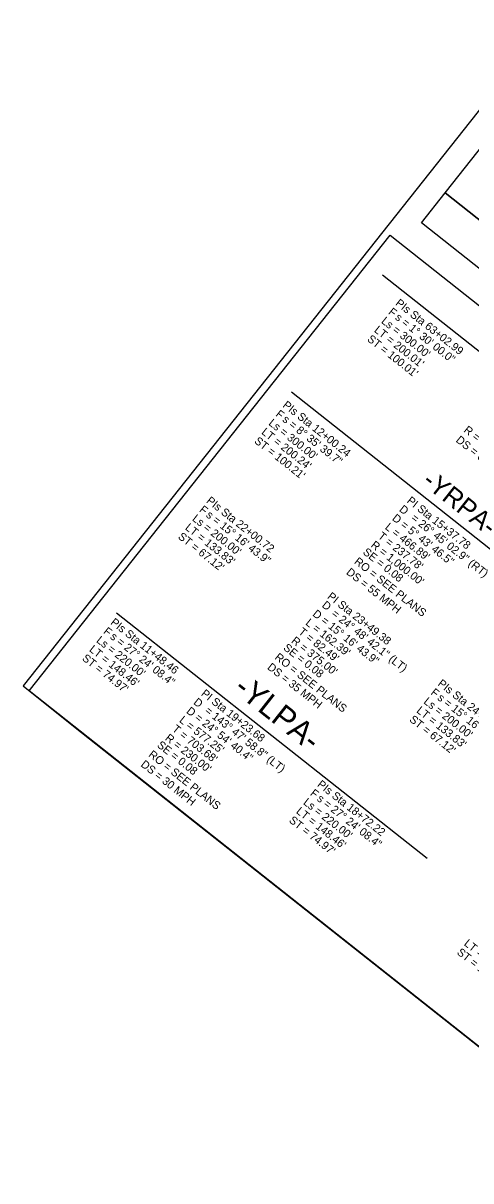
# Model space of a CAD drawing. Extents: x 1771636 to 1784627, y 798645 to 819978.
# Drawn here: x 1782923 to 1783314, y 812169 to 813181 of the extents above; entities that cross this region are included whole.
import ezdxf

# ---------------------------------------------------------------- set-up
doc = ezdxf.new("R2010")
doc.units = 0
for name, color, linetype in [('Exist Utilities Sanitary Sewer Manhole CELL', 7, 'Continuous'), ('Exist Utilities Telephone Pole CELL', 7, 'Continuous'), ('Exist Utilities Water Fire Hydrant CELL', 7, 'Continuous'), ('Exist Vegetation Woods Line', 7, 'Continuous')]:
    doc.layers.add(name, color=color, linetype=linetype)

msp = doc.modelspace()

# ---------------------------------------------------------------- linework, layer by layer
at = {"layer": 'Exist Utilities Telephone Pole CELL'}
msp.add_lwpolyline([(1783384.7, 813185.4), (1782922.7, 812601.8), (1782968.4, 812565.5), (1783541, 812112.3), (1783700.5, 812313.7), (1783949.3, 812116.7), (1783784.1, 811908), (1783320.2, 811324), (1783286.6, 811356.7), (1783146.9, 811467.3), (1783125.1, 811467.6), (1783094.1, 811428.4), (1782948.7, 811547.7), (1782956.1, 811557), (1782756.8, 811714.8), (1782728.2, 811696), (1782447, 811920.2), (1782412.5, 811881.5), (1782072.9, 812146.5), (1782110.3, 812188.5), (1781507.5, 812669.1)], dxfattribs=at)
at = {"layer": 'Exist Utilities Water Fire Hydrant CELL'}
for p, q in [((1783236.9, 812961.2), (1783435.3, 812804.1)), ((1783157.4, 812858.8), (1783432, 812641.4)), ((1783004.5, 812665.8), (1783275.8, 812451))]:
    msp.add_line(p, q, dxfattribs=at)
at = {"layer": 'Exist Vegetation Woods Line'}
for points in [[(1783405.8, 813177.4), (1784088, 812637.3), (1783973.7, 812492.9), (1783291.5, 813033)], [(1783291.5, 813033), (1783973.7, 812492.9), (1783952.9, 812466.7), (1783270.8, 813006.7)], [(1783243.6, 812995.9), (1784039.7, 812365.6), (1783883.7, 812168.7), (1783700.5, 812313.7), (1783541, 812112.3), (1782928.1, 812597.5)]]:
    msp.add_lwpolyline(points, close=True, dxfattribs=at)

# ---------------------------------------------------------------- texts
at = {"layer": 'Exist Utilities Sanitary Sewer Manhole CELL'}
for s, rotation, p in [('PIs Sta 63+02.99', 321.7188, (1783247.6, 812935.4)), ('F', 321.7188, (1783241.4, 812927.6)), ("Ls = 300.00'", 321.7188, (1783235.2, 812919.7)), ('s = 1%%d 30\' 00.0"', 321.7188, (1783247.3, 812922.9)), ("LT = 200.01'", 321.7188, (1783229, 812911.9)), ("ST = 100.01'", 321.7188, (1783222.9, 812904)), ('PIs Sta 12+00.24', 321.6243, (1783149.1, 812846.2)), ('F', 321.6243, (1783142.9, 812838.3)), ("Ls = 300.00'", 321.6243, (1783136.7, 812830.5)), ('s = 8%%d 35\' 39.7"', 321.6243, (1783148.8, 812833.7)), ("R = 5,729.58'", 321.7188, (1783307.3, 812824.4)), ("ST = 100.21'", 321.6243, (1783124.3, 812814.8)), ("LT = 200.24'", 321.6243, (1783130.5, 812822.7)), ('DS = 60 MPH', 321.7188, (1783300.4, 812815.7)), ('PIs Sta 22+00.72', 321.6243, (1783082.4, 812762.6)), ('PI Sta 15+37.78', 321.6243, (1783257.6, 812762.6)), ('F', 321.6243, (1783076.2, 812754.7)), ('D', 321.6243, (1783250.9, 812755.1)), ("Ls = 200.00'", 321.6243, (1783070, 812746.9)), ('s = 15%%d 16\' 43.9"', 321.6243, (1783082.1, 812750.1)), ('D = 5%%d 43\' 46.5"', 321.6243, (1783244.7, 812747.3)), ('= 26%%d 45\' 02.9" (RT)', 321.6243, (1783261.2, 812747.4)), ("LT = 133.83'", 321.6243, (1783063.8, 812739.1)), ("T = 237.78'", 321.6243, (1783232.3, 812731.6)), ("L = 466.89'", 321.6243, (1783238.5, 812739.5)), ("ST = 67.12'", 321.6243, (1783057.6, 812731.2)), ("R = 1,000.00'", 321.6243, (1783226.1, 812723.8)), ('SE = 0.08', 321.6243, (1783219.1, 812717.7)), ('RO = SEE PLANS', 321.6243, (1783211.6, 812709.4)), ('DS = 55 MPH', 321.7188, (1783204.6, 812700.1)), ('D', 321.4648, (1783183.3, 812671.3)), ('PI Sta 23+49.38', 321.6243, (1783188.1, 812678.9)), ('D = 15%%d 16\' 43.9"', 321.6243, (1783175.2, 812663.6)), ('= 24%%d 48\' 42.1" (LT)', 321.6243, (1783191.7, 812663.7)), ('PIs Sta 11+48.46', 321.7377, (1782998.6, 812656.2)), ("L = 162.39'", 321.6243, (1783169, 812655.8)), ("Ls = 220.00'", 321.7377, (1782986.2, 812640.5)), ('F', 321.7377, (1782992.4, 812648.3)), ('s = 27%%d 24\' 08.4"', 321.7377, (1782998.3, 812643.7)), ("T = 82.49'", 321.6243, (1783162.8, 812647.9)), ("LT = 148.46'", 321.7377, (1782980, 812632.6)), ('SE = 0.08', 321.6243, (1783149.6, 812634)), ("R = 375.00'", 321.6243, (1783156.6, 812640.1)), ("ST = 74.97'", 321.7377, (1782973.8, 812624.8)), ('RO = SEE PLANS', 321.6243, (1783142.1, 812625.7)), ('DS = 35 MPH', 321.7188, (1783135.6, 812617)), ('PIs Sta 24+96.40', 321.6243, (1783284.6, 812602.7)), ('PI Sta 19+23.68', 321.7377, (1783077.8, 812593.9)), ('F', 321.6243, (1783278.4, 812594.8)), ('D', 321.7377, (1783071.1, 812586.4)), ("Ls = 200.00'", 321.6243, (1783272.2, 812587)), ('s = 15%%d 16\' 43.9"', 321.6243, (1783284.3, 812590.2)), ("L = 577.25'", 321.7377, (1783058.7, 812570.7)), ('D = 24%%d 54\' 40.4"', 321.7377, (1783064.9, 812578.6)), ('= 143%%d 47\' 58.8" (LT)', 321.7377, (1783080.9, 812578.9)), ("ST = 67.12'", 321.6243, (1783259.8, 812571.3)), ("LT = 133.83'", 321.6243, (1783266, 812579.1)), ("T = 703.68'", 321.7377, (1783052.5, 812562.9)), ("R = 230.00'", 321.7377, (1783046.3, 812555)), ('RO = SEE PLANS', 321.6243, (1783031.8, 812540.6)), ('SE = 0.08', 321.6243, (1783039.3, 812548.9)), ('DS = 30 MPH', 321.7188, (1783025, 812532)), ('PIs Sta 18+72.22', 321.7377, (1783179.3, 812514.5)), ("Ls = 220.00'", 321.7377, (1783167, 812498.8)), ('F', 321.7377, (1783173.1, 812506.7)), ('s = 27%%d 24\' 08.4"', 321.7377, (1783179, 812502)), ("LT = 148.46'", 321.7377, (1783160.8, 812491)), ("ST = 74.97'", 321.7377, (1783154.6, 812483.1)), ("LT = 204.56'", 321.6948, (1783307.5, 812375.4)), ("ST = 104.16'", 321.6948, (1783301.3, 812367.6))]:
    msp.add_text(s, height=7, rotation=rotation, dxfattribs=at).set_placement(p)
at = {"layer": 'Exist Utilities Water Fire Hydrant CELL'}
for s, height, p in [('-YRPA-', 16.4, (1783270.6, 812778.7)), ('-YLPA-', 20, (1783105.7, 812597.3))]:
    msp.add_text(s, height=height, rotation=321.6309, dxfattribs=at).set_placement(p)

doc.saveas('drawing.dxf')
